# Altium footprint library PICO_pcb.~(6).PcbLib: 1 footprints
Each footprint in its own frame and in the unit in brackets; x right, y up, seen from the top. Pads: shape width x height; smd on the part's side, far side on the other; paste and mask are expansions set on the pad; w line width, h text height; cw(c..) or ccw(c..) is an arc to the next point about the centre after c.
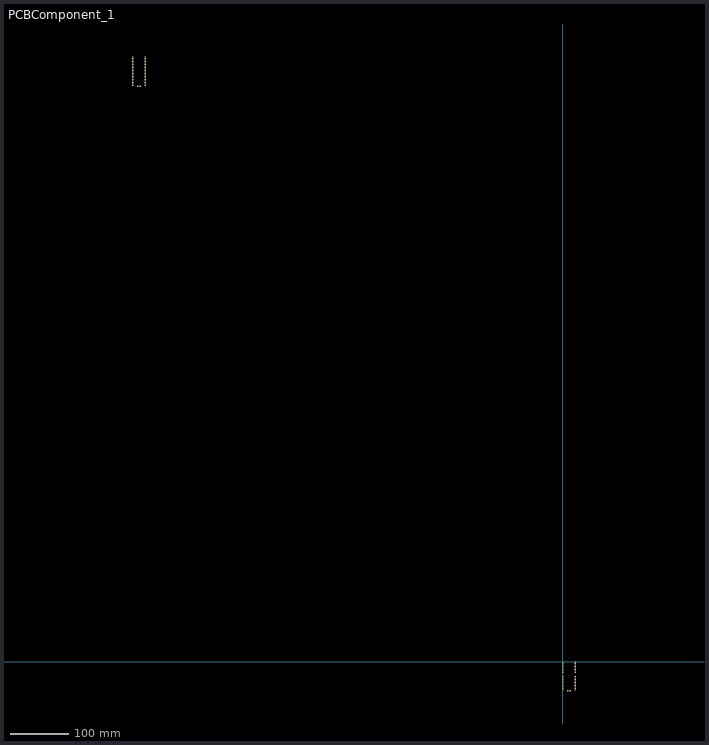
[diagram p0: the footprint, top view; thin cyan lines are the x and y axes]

## PCBComponent_1 [mm]
pads (86):
  rrect50% 2.5x1.6 smd: 1(-733.75,1031.75) 1(0,0) 2(-733.75,1029.21) 2(0,-2.54) 3(-733.75,1026.67) 3(0,-5.08) 4(-733.75,1024.13) 4(0,-7.62) 5(-733.75,1021.59) 5(0,-10.16) 6(-733.75,1019.05) 6(0,-12.7) 7(-733.75,1016.51) 7(0,-15.24) 8(-733.75,1013.97) 8(0,-17.78) 9(-733.75,1011.43) 9(0,-20.32) 10(-733.75,1008.89) 10(0,-22.86) 11(-733.75,1006.35) 11(0,-25.4) 12(-733.75,1003.81) 12(0,-27.94) 13(-733.75,1001.27) 13(0,-30.48) 14(-733.75,998.73) 14(0,-33.02) 15(-733.75,996.19) 15(0,-35.56) 16(-733.75,993.65) 16(0,-38.1) 17(-733.75,991.11) 17(0,-40.64) 18(-733.75,988.57) 18(0,-43.18) 19(-733.75,986.03) 19(0,-45.72) 20(-733.75,983.49) 20(0,-48.26) 21(-712.75,983.49) 21(21,-48.26) 22(-712.75,986.03) 22(21,-45.72) 23(-712.75,988.57) 23(21,-43.18) 24(-712.75,991.11) 24(21,-40.64) 25(-712.75,993.65) 25(21,-38.1) 26(-712.75,996.19) 26(21,-35.56) 27(-712.75,998.73) 27(21,-33.02) 28(-712.75,1001.27) 28(21,-30.48) 29(-712.75,1003.81) 29(21,-27.94) 30(-712.75,1006.35) 30(21,-25.4) 31(-712.75,1008.89) 31(21,-22.86) 32(-712.75,1011.43) 32(21,-20.32) 33(-712.75,1013.97) 33(21,-17.78) 34(-712.75,1016.51) 34(21,-15.24) 35(-712.75,1019.05) 35(21,-12.7) 36(-712.75,1021.59) 36(21,-10.16) 37(-712.75,1024.13) 37(21,-7.62) 38(-712.75,1026.67) 38(21,-5.08) 39(-712.75,1029.21) 39(21,-2.54) 40(-712.75,1031.75) 40(21,0)
  rrect50% 1.6x2.5 smd: 21(-725.79,982.12) 21(-723.25,982.12) 21(-720.71,982.12) 21(7.96,-49.63) 21(10.5,-49.63) 21(13.04,-49.63)
Bottom Overlay:
  lines w0.254: -736.75,980 -710,980 ; -736.75,980 -736.75,980 ; -736.75,980 -736.75,1033.25 -736.25,1033.75 -710,1033.75 -710,980 ; -710,980 -710,980 ; -3,-51.75 23.75,-51.75 ; -3,-51.75 -3,-51.75 ; -3,-51.75 -3,1.5 -2.5,2 23.75,2 23.75,-51.75 ; 23.75,-51.75 23.75,-51.75
3D body "Pico-R3.step": height 0, standoff -52.3, extent -765,992.5 -744,996.23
